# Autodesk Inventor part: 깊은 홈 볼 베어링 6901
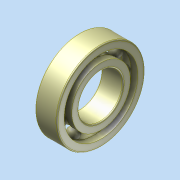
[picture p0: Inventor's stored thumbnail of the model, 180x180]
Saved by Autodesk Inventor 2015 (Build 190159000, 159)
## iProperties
Created: 2024-06
Part Number: 깊은 홈 볼 베어링 6901
Material: 일반
Document SubType Name: Modeling
Designer: Administrator
Density: 1 g/cm^3
Appearance: 기본값
Author: Administrator
Author: jhkim
Description: 깊은 그루브 볼 베어링
Creation Date: 2024-05-29
Sending System: Autodesk Inventor 2025
Preprocessor: ST-DEVELOPER v20
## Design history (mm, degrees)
node "깊은 홈 볼 베어링 69011"
body "Solid1"
node "Solid1_1"
node "Solid1_2"
node "Solid1_3"
node "Solid1_4"
node "Solid1_5"
node "Solid1_6"
node "Solid1_7"
node "Solid1_8"
node "Solid1_9"
node "Solid1_10"
node "기준1"
node "기준2"
node "기준3"
node "기준4"
node "기준5"
node "기준6"
node "기준7"
node "기준8"
node "기준9"
node "기준10"
node "기준11"
